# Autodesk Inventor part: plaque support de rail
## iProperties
Shininess: 64.0
Length Units: 11269
Angle Units: 11279
Time Units: 11290
Mass Units: 11283
Length Display Precision: 3
Angle Display Precision: 2
Compacted: True
Part Number: plaque support de rail
Document SubType Name: Modeling
Created: 2005-02
Material: Par défaut
Designer: LEGERET Philippe
Density: 0.0
Volumn: 0.0
Area: 0.0
PropertySet Name: Model Information
Control State: 0
Master: False
Checked Out: False
Author: LEGERET Philippe
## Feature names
1. Extrusion1
2. Chanfrein1 [Chamfer]
3. Perçage1 [Hole]
